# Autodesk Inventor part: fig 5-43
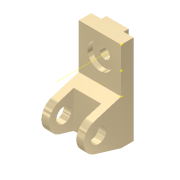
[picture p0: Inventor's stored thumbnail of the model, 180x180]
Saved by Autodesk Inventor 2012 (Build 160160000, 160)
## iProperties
Shininess: 65.0
Angle Display Precision: 2
Document Length Units: 11269
Document Angle Units: 11279
Document Time Units: 11290
Document Mass Units: 11283
Document Length Units Precision: 3
Document Angle Units Precision: 2
Created: 2001-11
Part Number: fig 5-43
Document SubType Name: Modeling
Designer: Renu Muthoo
Density: 1 g/cm^3
Material: Default
Density: 0.0
Volumn: 0.0
Area: 0.0
PropertySet Name: Model Information
Control State: 0
Master: False
Checked Out: False
Author: Renu Muthoo
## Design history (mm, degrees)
node "Sketch1"
sketch "Sketch2"
  geometry: L1 (33.257, 104.664)-(33.257, -75.336); L2 (33.257, -75.336)-(8.257, -75.336); L3 (8.257, -75.336)-(-45.451, -59.045); L4 (-45.451, -1.628)-(8.257, 14.664); L5 (8.257, 14.664)-(8.257, 104.664); L6 (8.257, 104.664)-(33.257, 104.664); C1 r 15 at (-36.743, -30.336); A1 r 30 centre (-36.743, -30.336) between (-45.451, -1.628) and (-45.451, -59.045)
  constraints: 12 end point, 2 centre point, 2 equal length, 2 parallel, 2 point on circle, 2 tangent, 1 coincident, 1 perpendicular, 1 vertical
  dimensions: "d0" = 180 distance of L1.start L1.end; "d1" = 30 radius of A1; "d2" = 25 distance of L5.end L1.start; "d3" = 45 distance from line of L2 A1.centre; "d4" = 70 distance from line of L1 A1.centre; "d5" = 30 diameter of C1
extrude "Extrusion1" new body sketch "Sketch2" distance "d6" = 85; taper "d7" = 0 deg
workplane "Work Plane1"
sketch "Sketch3"
  geometry: L1 (15, 62.364)-(70, 62.364); L2 (70, 62.364)-(70, -52.386); L3 (70, -52.386)-(15, -52.386); L4 (15, -52.386)-(15, 62.364); L5 (0, -45)-(0, -28.708) reference
  constraints: 8 end point, 2 parallel, 1 horizontal, 1 perpendicular
  dimensions: "d8" = 55 distance of L1.start L1.end; "d9" = 15 distance between parallel lines of L5 L4
extrude "Extrusion2" cut sketch "Sketch3" distance "d10" = 50; taper "d11" = 0 deg
sketch "Sketch4"
  geometry: L1 (0, 25)-(85, 25) reference; L2 (0, 0)-(0, 25) reference; L3 (20, 25)-(65, 25); L4 (65, 25)-(65, 35); L5 (65, 35)-(20, 35); L6 (20, 35)-(20, 25)
  constraints: 8 end point, 2 parallel, 1 horizontal, 1 perpendicular, 1 point on line
  dimensions: "d12" = 45 distance of L4.end L5.end; "d13" = 10 distance of L3.end L4.end; "d14" = 20 distance between parallel lines of L2 L6
extrude "Extrusion3" join sketch "Sketch4" stored distance "d15" = 50; taper "d16" = 0 deg
sketch "Sketch5"
  geometry: L1 (85, 0)-(85, 90) reference; L2 (0, 90)-(85, 90) reference; 1 further point
  dimensions: "d17" = 42 distance from line of L2 point (42.5, 48); "d18" = 42.5 distance from line of L1 point (42.5, 48)
hole "Hole1" sketch "Sketch5" at (42.5, 48) diameter "d19" = 20; stored, may be unused: countersink angle "d23" = 82 deg, drill point angle "d25" = 118 deg; dims "d20" = 6, "d21" = 50, "d22" = 10, "d24" = 8
workpoint "Work Point1"
workpoint "Work Point2"
workpoint "Work Point3"
workpoint "Work Point4"
workaxis "Work Axis2"
body "Solid1"
